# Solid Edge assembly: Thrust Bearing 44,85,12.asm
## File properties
Title: Thrust Bearing 44,85,12
Author: Dan
Template: Normal.asm
Last saved by: Dan
Revision: 31
Application: Solid Edge
Document Number: P52-005
Project Name: Piston Pump P52
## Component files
Thrust Washer.par
Thrust Cage.asm
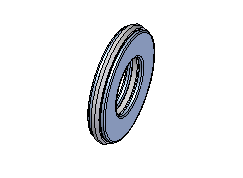
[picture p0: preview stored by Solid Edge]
